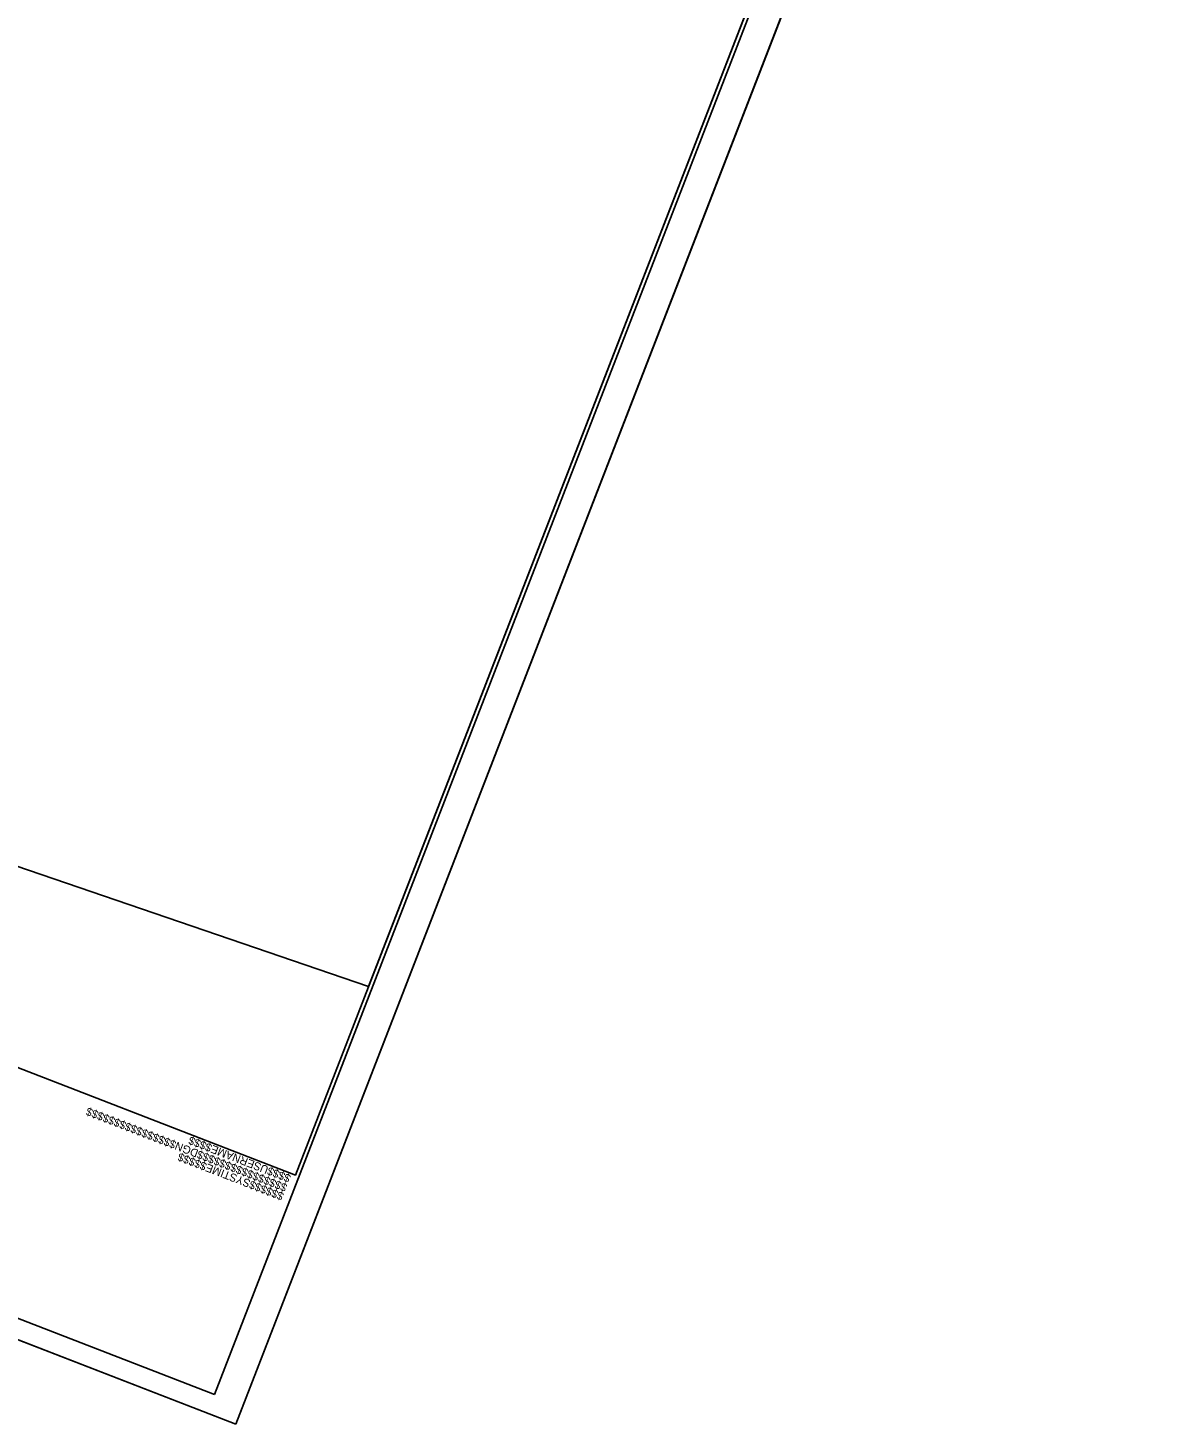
# Model space of a CAD drawing. Extents: x 1976816 to 1978446, y 780470 to 782626.
# Drawn here: x 1977701 to 1978446, y 780525 to 781441 of the extents above; entities that cross this region are included whole.
import ezdxf

# ---------------------------------------------------------------- set-up
doc = ezdxf.new("R2010")
doc.units = 0
for name, color, linetype in [('Sheet Clip Boundary CELL', 7, 'Continuous'), ('Sheet Cutting Line CELL', 7, 'Continuous'), ('Sheet Plan CELL', 7, 'Continuous'), ('Sheet Plan Layout CELL', 7, 'Continuous'), ('Sheet Plot Border Inside CELL', 7, 'Continuous'), ('Sheet Plot Border Outside CELL', 7, 'Continuous')]:
    doc.layers.add(name, color=color, linetype=linetype)

msp = doc.modelspace()

# ---------------------------------------------------------------- linework, layer by layer
at = {"layer": 'Sheet Clip Boundary CELL'}
msp.add_lwpolyline([(1977924.48, 780811.85), (1978376.74, 781979.06), (1978142.45, 782069.81), (1977652.42, 782318.2), (1977659.93, 782314.31), (1977564.08, 782202.56), (1977366.88, 782278.97), (1977352.17, 782241), (1977411.94, 782200.15), (1977347.77, 782229.66), (1976926.95, 781143.58), (1977039.99, 781140.98), (1977039.7, 781120.49), (1977166.45, 781076.01), (1977684.74, 780893.76)], close=True, dxfattribs=at)
at = {"layer": 'Sheet Cutting Line CELL'}
for p, q in [((1977837.35, 780524.67), (1978445.59, 782094.45)), ((1976816.32, 780920.29), (1977837.35, 780524.67))]:
    msp.add_line(p, q, dxfattribs=at)
at = {"layer": 'Sheet Plan CELL'}
msp.add_line((1977876.51, 780688.04), (1977876.51, 780688.04), dxfattribs=at)
for points in [[(1977439.39, 782466.12), (1976897.44, 781067.4), (1977876.51, 780688.04), (1978418.46, 782086.73)], [(1977876.51, 780688.04), (1976897.45, 781067.37), (1977367.09, 782279.56), (1977507.03, 782225.36), (1977579.31, 782411.88), (1978418.46, 782086.73)]]:
    msp.add_lwpolyline(points, close=True, dxfattribs=at)
at = {"layer": 'Sheet Plan Layout CELL'}
msp.add_lwpolyline([(1976897.45, 781067.37), (1977876.51, 780688.04), (1978418.45, 782086.72), (1977636.58, 782389.67), (1977550.14, 782166.58), (1977352.94, 782242.99)], close=True, dxfattribs=at)
at = {"layer": 'Sheet Plot Border Inside CELL'}
msp.add_lwpolyline([(1977823.4, 780544.02), (1978425.3, 782097.47), (1977441.58, 782478.65), (1976839.66, 780925.18)], close=True, dxfattribs=at)
at = {"layer": 'Sheet Plot Border Outside CELL'}
msp.add_lwpolyline([(1977837.35, 780524.67), (1978445.59, 782094.45), (1977424.56, 782490.07), (1976816.32, 780920.29)], close=True, dxfattribs=at)

# ---------------------------------------------------------------- texts
at = {"layer": 'Sheet Plan CELL'}
for s, p in [('$$$$$$$$$$$$$$$$DGN$$$$$$$$$$$$$$$$', (1977871.55, 780681.78)), ('$$$$USERNAME$$$$', (1977873.9, 780687.89)), ('$$$$$$SYSTIME$$$$$', (1977869.38, 780676.1))]:
    msp.add_text(s, height=5.25, rotation=158.82032, dxfattribs=at).set_placement(p)

doc.saveas('drawing.dxf')
